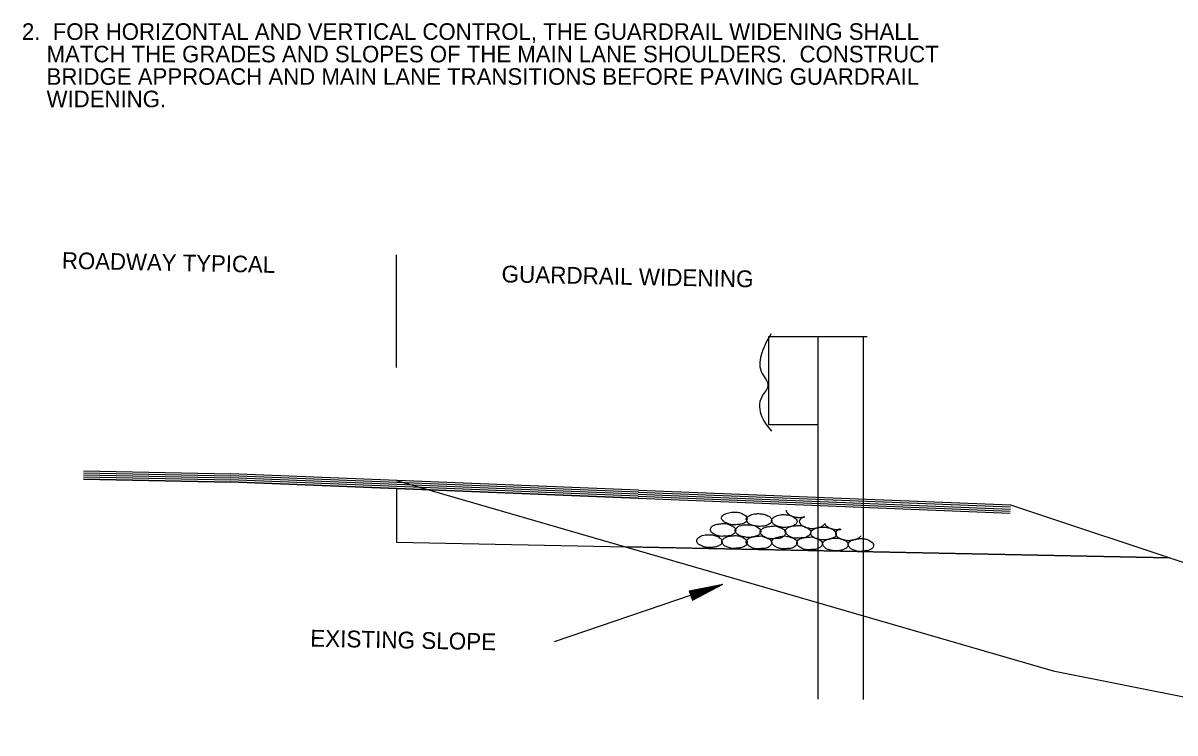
# Model space of a CAD drawing. Extents: x 1929624 to 1932072, y 596315 to 605533.
# Drawn here: x 1930695.1 to 1931111.9, y 604976 to 605232.9 of the extents above; entities that cross this region are included whole.
import ezdxf

# ---------------------------------------------------------------- set-up
doc = ezdxf.new("R2010")
doc.units = 0
doc.layers.add('Default', color=7, linetype='Continuous')
doc.layers.add('R_Border', color=7, linetype='Continuous')

msp = doc.modelspace()

# ---------------------------------------------------------------- linework, layer by layer
at = {"layer": 'Default'}
for p, q in [((1930964.85, 605119.43), (1930964.85, 605087.59)), ((1930964.85, 605119.43), (1931000.5, 605119.43)), ((1930982.69, 605119.43), (1930982.69, 604988.24)), ((1930999.07, 605119.28), (1930999.07, 604988.12)), ((1930964.85, 605087.59), (1930982.69, 605087.59)), ((1930716.94, 605070.86), (1930770.11, 605069.8)), ((1930716.94, 605070.12), (1930770.11, 605069.06)), ((1930716.97, 605069.38), (1930770.11, 605068.33)), ((1930716.99, 605068.65), (1930770.11, 605067.59)), ((1930717.02, 605067.91), (1930770.06, 605066.85)), ((1930717.02, 605067.81), (1930770.11, 605066.75)), ((1930917.64, 605060.94), (1930770.01, 605066.85)), ((1930917.69, 605062.42), (1930770.06, 605068.33)), ((1930917.69, 605061.68), (1930770.06, 605067.59)), ((1930917.73, 605063.9), (1930770.11, 605069.8)), ((1930917.73, 605063.16), (1930770.11, 605069.06)), ((1930917.64, 605060.85), (1930770.11, 605066.75)), ((1930917.64, 605061.68), (1931052.29, 605056.29)), ((1930917.67, 605062.42), (1931052.33, 605057.03)), ((1930917.69, 605063.16), (1931052.35, 605057.77)), ((1930917.73, 605063.9), (1931052.39, 605058.51)), ((1930917.61, 605060.94), (1931052.27, 605055.56)), ((1931052.39, 605058.51), (1931287.4, 604980.38)), ((1930887.41, 605009.14), (1930948.32, 605029.82)), ((1930936.09, 605027.48), (1930948.32, 605029.82)), ((1930936.17, 605027.22), (1930946.39, 605029.16)), ((1930936.31, 605026.9), (1930944.32, 605028.42)), ((1930937.05, 605024.65), (1930944.32, 605028.42)), ((1930937.16, 605024.31), (1930946.39, 605029.16)), ((1930937.29, 605024.03), (1930948.32, 605029.82)), ((1930936.09, 605027.48), (1930937.29, 605024.03)), ((1930936.4, 605026.6), (1930942.4, 605027.75)), ((1930936.52, 605026.29), (1930940.48, 605027.07)), ((1930936.56, 605025.99), (1930938.51, 605026.38)), ((1930936.79, 605025.49), (1930938.51, 605026.38)), ((1930936.88, 605025.18), (1930940.48, 605027.07)), ((1930937, 605024.92), (1930942.4, 605027.75))]:
    msp.add_line(p, q, dxfattribs=at)
for points in [[(1930965.71, 605120.46), (1930962.37, 605113.55), (1930962.19, 605106.81), (1930964.6, 605101.61), (1930962.37, 605097.68), (1930962.37, 605090.42), (1930965.91, 605085.18)], [(1930952.6, 605055.88), (1930950.97, 605055.79), (1930949.01, 605055.2), (1930947.97, 605054.26), (1930947.82, 605053.72), (1930948.32, 605052.74), (1930948.91, 605052.29), (1930950.04, 605051.75), (1930951.61, 605051.31), (1930952.45, 605051.31), (1930953.63, 605051.41), (1930954.96, 605051.55), (1930955.99, 605051.95), (1930956.88, 605052.78), (1930957.03, 605053.42), (1930956.73, 605054.31), (1930956.09, 605054.9), (1930955.4, 605055.29), (1930954.32, 605055.74), (1930953.63, 605055.88), (1930952.6, 605055.88)], [(1930961.41, 605055.36), (1930959.79, 605055.26), (1930957.87, 605054.57), (1930956.89, 605053.78), (1930956.74, 605053.24), (1930957.28, 605052.21), (1930957.72, 605051.67), (1930958.9, 605051.18), (1930960.38, 605050.83), (1930961.22, 605050.73), (1930962.45, 605050.78), (1930963.83, 605051.03), (1930964.81, 605051.47), (1930965.84, 605052.26), (1930965.99, 605052.9), (1930965.7, 605053.78), (1930964.96, 605054.42), (1930964.22, 605054.77), (1930963.14, 605055.11), (1930962.45, 605055.26), (1930961.41, 605055.36)], [(1930970.59, 605054.99), (1930968.97, 605054.94), (1930967, 605054.25), (1930966.02, 605053.37), (1930965.87, 605052.78), (1930966.41, 605051.79), (1930966.95, 605051.35), (1930968.03, 605050.86), (1930969.61, 605050.41), (1930970.44, 605050.36), (1930971.62, 605050.46), (1930972.95, 605050.71), (1930973.99, 605051.1), (1930974.97, 605051.89), (1930975.12, 605052.48), (1930974.82, 605053.37), (1930974.09, 605053.96), (1930973.4, 605054.45), (1930972.31, 605054.79), (1930971.62, 605054.94), (1930970.59, 605054.99)], [(1930971.21, 605056.58), (1930971.21, 605056.55), (1930971.21, 605056.48), (1930971.22, 605056.42), (1930971.29, 605056.15), (1930971.41, 605055.89), (1930971.56, 605055.63), (1930971.66, 605055.5), (1930971.76, 605055.38), (1930972.01, 605055.13), (1930972.3, 605054.94), (1930972.56, 605054.8), (1930972.83, 605054.67), (1930973.1, 605054.55), (1930973.38, 605054.45), (1930974.16, 605054.23), (1930974.96, 605054.06), (1930975.37, 605053.99), (1930975.58, 605053.97), (1930975.79, 605053.96), (1930976.38, 605053.99), (1930976.68, 605054.02), (1930976.97, 605054.06), (1930977.49, 605054.14), (1930978.01, 605054.24)], [(1930977.87, 605054.29), (1930977.57, 605054.17), (1930977.33, 605054.05), (1930977.09, 605053.93), (1930976.8, 605053.75), (1930976.54, 605053.53), (1930976.32, 605053.29), (1930976.21, 605053.15), (1930976.1, 605053), (1930976.03, 605052.86), (1930975.98, 605052.73), (1930975.95, 605052.59), (1930975.95, 605052.52), (1930975.96, 605052.46), (1930976.03, 605052.19), (1930976.15, 605051.92), (1930976.3, 605051.67), (1930976.4, 605051.54), (1930976.5, 605051.42), (1930976.75, 605051.17), (1930977.04, 605050.98), (1930977.3, 605050.84), (1930977.57, 605050.7), (1930977.84, 605050.59), (1930978.12, 605050.49), (1930978.9, 605050.27), (1930979.7, 605050.09), (1930980.53, 605050), (1930980.68, 605050), (1930980.83, 605050), (1930981.12, 605050.02), (1930981.71, 605050.09), (1930982.05, 605050.14), (1930982.38, 605050.2), (1930982.71, 605050.27), (1930983.04, 605050.34), (1930983.31, 605050.41), (1930983.57, 605050.51), (1930983.82, 605050.61), (1930984.08, 605050.73), (1930984.35, 605050.88), (1930984.61, 605051.05), (1930984.84, 605051.26), (1930984.95, 605051.38), (1930985.06, 605051.52), (1930985.13, 605051.64), (1930985.18, 605051.76)], [(1930948.52, 605051.78), (1930946.8, 605051.58), (1930944.88, 605051.09), (1930943.9, 605050.15), (1930943.75, 605049.61), (1930944.24, 605048.58), (1930944.83, 605048.13), (1930945.91, 605047.54), (1930947.49, 605047.15), (1930948.28, 605047.15), (1930949.51, 605047.25), (1930950.88, 605047.35), (1930951.92, 605047.84), (1930952.8, 605048.68), (1930952.95, 605049.32), (1930952.66, 605050.2), (1930951.92, 605050.79), (1930951.23, 605051.09), (1930950.15, 605051.53), (1930949.51, 605051.73), (1930948.52, 605051.78)], [(1930957.45, 605051.36), (1930955.83, 605051.31), (1930953.86, 605050.67), (1930952.88, 605049.73), (1930952.73, 605049.19), (1930953.27, 605048.16), (1930953.81, 605047.72), (1930954.89, 605047.22), (1930956.47, 605046.83), (1930957.31, 605046.73), (1930958.49, 605046.83), (1930959.81, 605047.08), (1930960.85, 605047.47), (1930961.83, 605048.26), (1930961.98, 605048.9), (1930961.68, 605049.78), (1930960.95, 605050.37), (1930960.26, 605050.82), (1930959.18, 605051.16), (1930958.49, 605051.31), (1930957.45, 605051.36)], [(1930966.55, 605050.86), (1930964.92, 605050.71), (1930962.96, 605050.17), (1930961.92, 605049.23), (1930961.78, 605048.69), (1930962.32, 605047.71), (1930962.86, 605047.26), (1930963.99, 605046.63), (1930965.51, 605046.28), (1930966.35, 605046.28), (1930967.53, 605046.38), (1930968.96, 605046.43), (1930969.94, 605046.92), (1930970.88, 605047.76), (1930971.03, 605048.4), (1930970.73, 605049.28), (1930970.04, 605049.87), (1930969.3, 605050.22), (1930968.27, 605050.56), (1930967.58, 605050.86), (1930966.55, 605050.86)], [(1930975.5, 605051.09), (1930973.88, 605050.89), (1930971.96, 605050.4), (1930970.98, 605049.46), (1930970.83, 605048.92), (1930971.37, 605047.89), (1930971.91, 605047.45), (1930972.99, 605046.85), (1930974.57, 605046.46), (1930975.36, 605046.46), (1930976.59, 605046.56), (1930977.92, 605046.66), (1930979, 605047.15), (1930979.93, 605047.99), (1930980.08, 605048.63), (1930979.78, 605049.51), (1930979.05, 605050.1), (1930978.31, 605050.4), (1930977.28, 605050.89), (1930976.54, 605051.04), (1930975.5, 605051.09)], [(1930984.8, 605050.45), (1930983.18, 605050.4), (1930981.21, 605049.76), (1930980.23, 605048.82), (1930980.08, 605048.28), (1930980.62, 605047.25), (1930981.16, 605046.81), (1930982.25, 605046.31), (1930983.82, 605045.92), (1930984.66, 605045.82), (1930985.84, 605045.92), (1930987.17, 605046.17), (1930988.2, 605046.56), (1930989.18, 605047.35), (1930989.33, 605047.99), (1930989.04, 605048.87), (1930988.3, 605049.46), (1930987.61, 605049.91), (1930986.53, 605050.25), (1930985.84, 605050.4), (1930984.8, 605050.45)], [(1930985.13, 605051.78), (1930985.21, 605051.58), (1930985.32, 605051.38), (1930985.45, 605051.18), (1930985.6, 605051), (1930985.86, 605050.75), (1930986.14, 605050.55), (1930986.41, 605050.41), (1930986.67, 605050.28), (1930986.94, 605050.16), (1930987.22, 605050.06), (1930988.01, 605049.84), (1930988.8, 605049.67), (1930989.22, 605049.6), (1930989.43, 605049.58), (1930989.64, 605049.57), (1930990.23, 605049.6), (1930990.82, 605049.67), (1930991.12, 605049.71)], [(1930990.7, 605049.85), (1930990.44, 605049.74), (1930990.31, 605049.67), (1930990.18, 605049.6), (1930989.88, 605049.42), (1930989.63, 605049.2), (1930989.4, 605048.96), (1930989.3, 605048.82), (1930989.19, 605048.67), (1930989.11, 605048.53), (1930989.06, 605048.4), (1930989.04, 605048.26), (1930989.04, 605048.19), (1930989.04, 605048.12), (1930989.12, 605047.86), (1930989.23, 605047.59), (1930989.39, 605047.34), (1930989.48, 605047.21), (1930989.58, 605047.09), (1930989.84, 605046.84), (1930990.13, 605046.65), (1930990.39, 605046.5), (1930990.66, 605046.37), (1930990.93, 605046.26), (1930991.21, 605046.16), (1930991.99, 605045.94), (1930992.78, 605045.76), (1930993.62, 605045.66), (1930993.77, 605045.67), (1930993.91, 605045.67), (1930994.21, 605045.69), (1930994.8, 605045.76), (1930995.14, 605045.81), (1930995.47, 605045.87), (1930995.8, 605045.94), (1930996.13, 605046.01), (1930996.4, 605046.08), (1930996.65, 605046.18), (1930996.91, 605046.28), (1930997.16, 605046.4), (1930997.44, 605046.55), (1930997.7, 605046.72), (1930997.93, 605046.93), (1930998.04, 605047.05), (1930998.09, 605047.12), (1930998.15, 605047.19), (1930998.19, 605047.27)], [(1930943.5, 605047.68), (1930941.88, 605047.63), (1930939.91, 605046.95), (1930938.98, 605046.06), (1930938.83, 605045.47), (1930939.32, 605044.48), (1930939.91, 605044.04), (1930940.94, 605043.55), (1930942.57, 605043.11), (1930943.36, 605043.06), (1930944.59, 605043.16), (1930945.91, 605043.4), (1930946.95, 605043.8), (1930947.88, 605044.58), (1930948.03, 605045.17), (1930947.73, 605046.06), (1930947, 605046.65), (1930946.31, 605047.14), (1930945.22, 605047.49), (1930944.54, 605047.63), (1930943.5, 605047.68)], [(1930952.61, 605047.4), (1930950.98, 605047.25), (1930949.01, 605046.66), (1930948.08, 605045.77), (1930947.93, 605045.18), (1930948.42, 605044.2), (1930948.92, 605043.75), (1930950.05, 605043.26), (1930951.57, 605042.77), (1930952.41, 605042.77), (1930953.64, 605042.87), (1930955.02, 605043.07), (1930956, 605043.41), (1930956.99, 605044.3), (1930957.13, 605044.89), (1930956.84, 605045.77), (1930956.1, 605046.36), (1930955.36, 605046.81), (1930954.33, 605047.2), (1930953.64, 605047.35), (1930952.61, 605047.4)], [(1930961.46, 605047.26), (1930959.83, 605047.07), (1930957.86, 605046.53), (1930956.88, 605045.64), (1930956.73, 605045.05), (1930957.27, 605044.07), (1930957.81, 605043.62), (1930958.9, 605043.03), (1930960.42, 605042.64), (1930961.26, 605042.64), (1930962.49, 605042.74), (1930963.82, 605042.84), (1930964.85, 605043.28), (1930965.83, 605044.16), (1930965.98, 605044.76), (1930965.69, 605045.64), (1930964.95, 605046.23), (1930964.21, 605046.58), (1930963.13, 605046.97), (1930962.49, 605047.22), (1930961.46, 605047.26)], [(1930970.71, 605047.27), (1930969.04, 605047.08), (1930967.07, 605046.53), (1930966.09, 605045.65), (1930965.94, 605045.06), (1930966.48, 605044.07), (1930967.02, 605043.63), (1930968.16, 605042.99), (1930969.68, 605042.65), (1930970.47, 605042.65), (1930971.7, 605042.7), (1930973.08, 605042.84), (1930974.11, 605043.29), (1930975.04, 605044.17), (1930975.19, 605044.76), (1930974.9, 605045.65), (1930974.16, 605046.24), (1930973.42, 605046.58), (1930972.39, 605046.93), (1930971.75, 605047.13), (1930970.71, 605047.27)], [(1930979.78, 605046.9), (1930978.06, 605046.71), (1930976.19, 605046.22), (1930975.16, 605045.28), (1930975.01, 605044.74), (1930975.55, 605043.71), (1930976.09, 605043.26), (1930977.23, 605042.67), (1930978.75, 605042.28), (1930979.54, 605042.28), (1930980.77, 605042.38), (1930982.2, 605042.48), (1930983.18, 605042.97), (1930984.12, 605043.8), (1930984.26, 605044.44), (1930983.97, 605045.33), (1930983.23, 605045.92), (1930982.54, 605046.22), (1930981.46, 605046.61), (1930980.82, 605046.85), (1930979.78, 605046.9)], [(1930989.06, 605046.53), (1930987.44, 605046.43), (1930985.52, 605045.74), (1930984.53, 605044.95), (1930984.39, 605044.41), (1930984.93, 605043.38), (1930985.37, 605042.84), (1930986.55, 605042.34), (1930988.03, 605042), (1930988.86, 605041.9), (1930990.09, 605041.95), (1930991.47, 605042.2), (1930992.46, 605042.64), (1930993.49, 605043.43), (1930993.64, 605044.07), (1930993.34, 605044.95), (1930992.6, 605045.59), (1930991.87, 605045.94), (1930990.78, 605046.28), (1930990.09, 605046.43), (1930989.06, 605046.53)], [(1930998.31, 605046.34), (1930996.69, 605046.19), (1930994.72, 605045.6), (1930993.78, 605044.71), (1930993.64, 605044.12), (1930994.13, 605043.14), (1930994.62, 605042.7), (1930995.75, 605042.2), (1930997.28, 605041.71), (1930998.11, 605041.71), (1930999.34, 605041.81), (1931000.72, 605042.01), (1931001.71, 605042.35), (1931002.69, 605043.24), (1931002.84, 605043.83), (1931002.54, 605044.71), (1931001.81, 605045.3), (1931001.07, 605045.75), (1931000.03, 605046.14), (1930999.34, 605046.29), (1930998.31, 605046.34)]]:
    msp.add_spline(points, degree=3, dxfattribs=at)
at = {"layer": 'R_Border'}
for p, q in [((1930830.21, 605108.18), (1930830.21, 605148.95)), ((1931109.84, 605039.42), (1930913.15, 605043.33))]:
    msp.add_line(p, q, dxfattribs=at)
for points in [[(1930830.21, 605067.4), (1931067.75, 604998.46), (1931172.64, 604977.6), (1931225.49, 604976), (1931273.1, 604980.37), (1931377.3, 604980.38)], [(1930830.21, 605064.35), (1930830.21, 605044.98), (1931109.84, 605039.42)]]:
    msp.add_lwpolyline(points, dxfattribs=at)

# ---------------------------------------------------------------- texts
at = {"layer": 'Default'}
for s, p in [('2.  FOR HORIZONTAL AND VERTICAL CONTROL, THE GUARDRAIL WIDENING SHALL', (1930694.71, 605226.79)), ('    MATCH THE GRADES AND SLOPES OF THE MAIN LANE SHOULDERS.  CONSTRUCT', (1930694.71, 605218.66)), ('    BRIDGE APPROACH AND MAIN LANE TRANSITIONS BEFORE PAVING GUARDRAIL', (1930694.71, 605210.53)), ('    WIDENING.', (1930694.71, 605202.41))]:
    msp.add_text(s, height=6, dxfattribs=at).set_placement(p)
for s, height, p in [('ROADWAY TYPICAL', 6, (1930709.13, 605143.99)), ('GUARDRAIL WIDENING', 6.075, (1930868.18, 605139.06)), ('EXISTING SLOPE', 6.075, (1930798.97, 605007.27))]:
    msp.add_text(s, height=height, rotation=358.8537, dxfattribs=at).set_placement(p)

doc.saveas('drawing.dxf')
